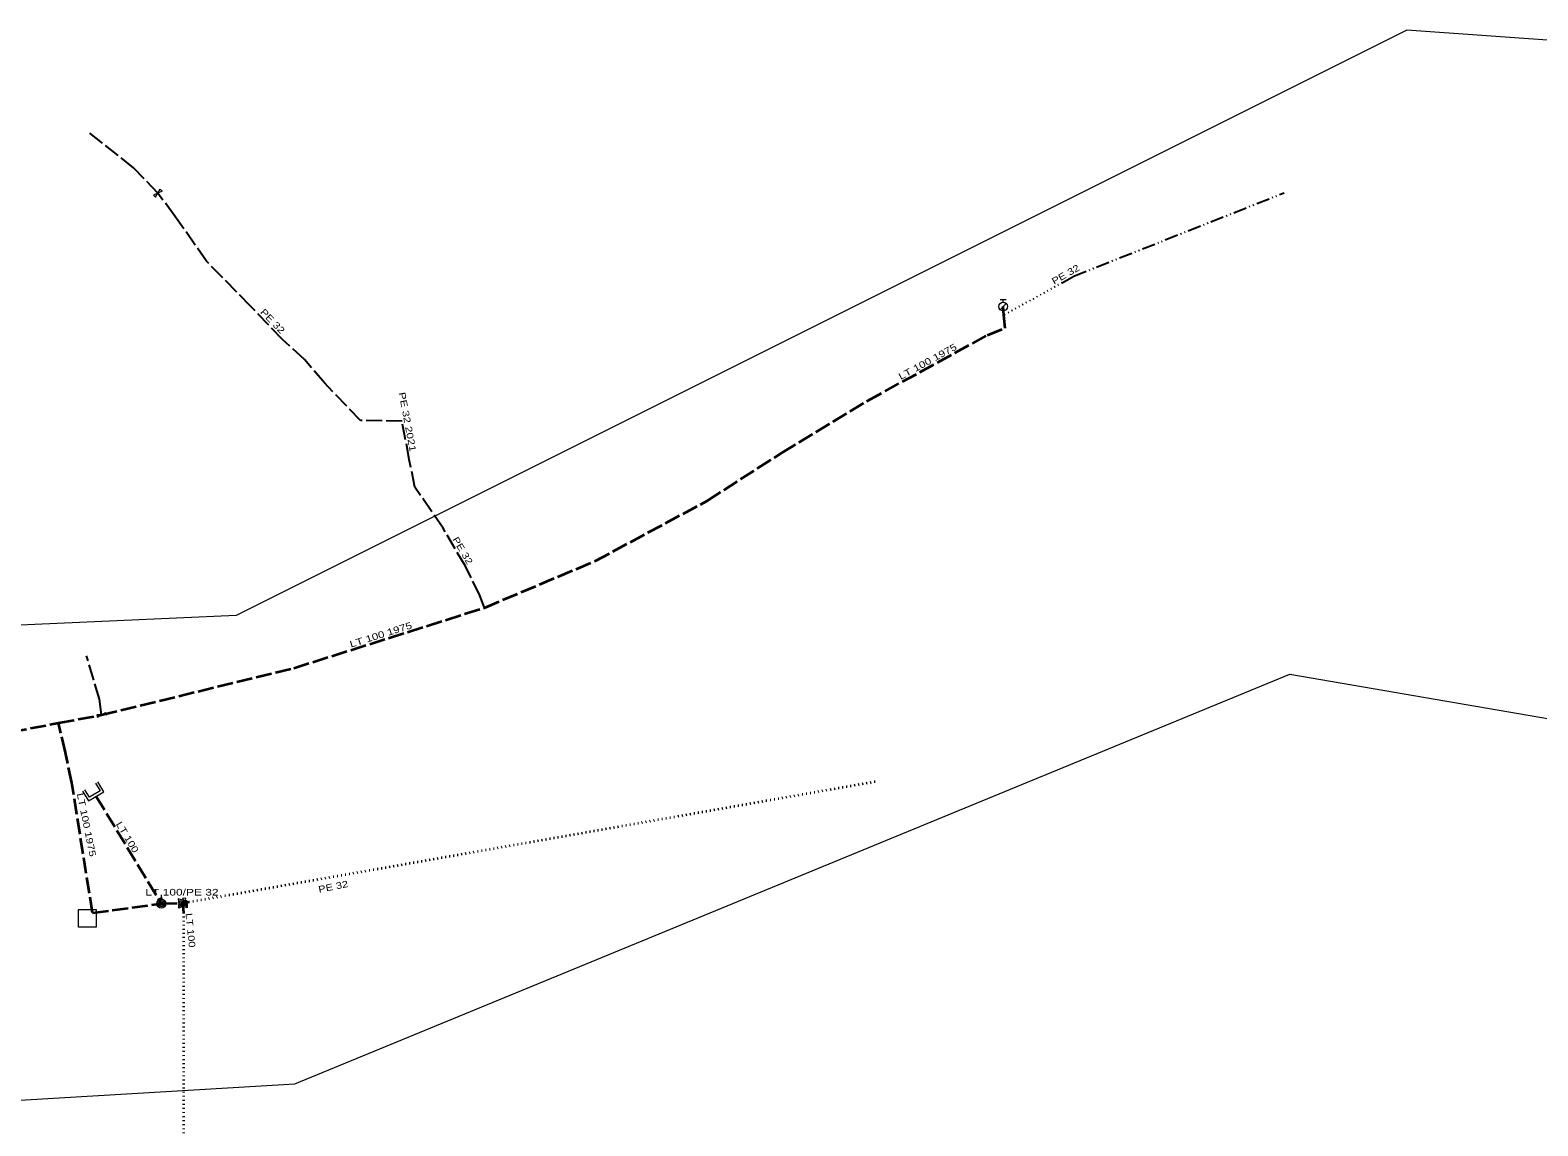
# Model space of a CAD drawing. Extents: x -582626 to -580899, y -1097611 to -1096610.
# Drawn here: x -581240 to -581069.6, y -1096737.9 to -1096614.1 of the extents above; entities that cross this region are included whole.
import ezdxf
from ezdxf.enums import TextEntityAlignment as Align

# ---------------------------------------------------------------- set-up
doc = ezdxf.new("R2010")
doc.units = 0
doc.header["$LTSCALE"] = 0.3
for name, pattern in [('DASH_DOUBLE_DOT', [9.2, 5, -1.2, 0.3, -1.2, 0.3, -1.2]), ('DOTTED', [1.5, 0.3, -1.2]), ('LONG_DASHED', [7.5, 6, -1.5])]:
    doc.linetypes.add(name, pattern=pattern)
for name, color, linetype, lineweight in [('1', 7, 'Continuous', 13), ('10', 7, 'Continuous', 13), ('35', 7, 'LONG_DASHED', 35), ('36', 7, 'DASH_DOUBLE_DOT', 35), ('45', 7, 'LONG_DASHED', 35), ('50', 7, 'LONG_DASHED', 25), ('51', 7, 'DOTTED', 25)]:
    doc.layers.add(name, color=color, linetype=linetype, lineweight=lineweight)
for name, color, linetype in [('16', 7, 'Continuous'), ('18', 7, 'Continuous'), ('19', 7, 'Continuous')]:
    doc.layers.add(name, color=color, linetype=linetype)

msp = doc.modelspace()

# ---------------------------------------------------------------- linework, layer by layer
at = {"layer": '1'}
msp.add_lwpolyline([(-582625.57, -1097394.66), (-582612.34, -1097467.421), (-582321.299, -1097262.369), (-581897.965, -1097202.837), (-581719.372, -1097182.994), (-581593.695, -1097110.233), (-581382.028, -1096971.327), (-581362.184, -1096819.192), (-581322.497, -1096739.817), (-581210.049, -1096733.202), (-581097.601, -1096686.9), (-580905.778, -1096719.973), (-580899.163, -1096627.369), (-581084.372, -1096614.14), (-581216.663, -1096680.285), (-581368.799, -1096686.9), (-581434.945, -1096812.577), (-581468.018, -1096971.327), (-581659.84, -1097004.4), (-581831.82, -1097110.233), (-582314.684, -1097169.765), (-582519.736, -1097295.442), (-582625.57, -1097394.66)], close=True, dxfattribs=at)
at = {"layer": '10'}
for p, q in [((-581130.337, -1096645.723), (-581129.63, -1096645.016)), ((-581130.333, -1096644.569), (-581129.633, -1096644.569)), ((-581129.983, -1096644.869), (-581129.983, -1096644.569)), ((-581225.134, -1096712.32), (-581225.275, -1096712.179)), ((-581222.238, -1096712.695), (-581222.262, -1096712.446)), ((-581222.691, -1096712.871), (-581222.941, -1096712.871))]:
    msp.add_line(p, q, dxfattribs=at)
for points in [[(-581225.526, -1096632.551), (-581225.246, -1096632.11), (-581225.05, -1096632.337), (-581225.526, -1096632.551), (-581226.002, -1096632.765), (-581225.806, -1096632.992)], [(-581231.902, -1096691.503), (-581231.455, -1096691.233), (-581231.38, -1096691.524), (-581231.902, -1096691.503), (-581232.424, -1096691.482), (-581232.349, -1096691.773)], [(-581223.224, -1096712.29), (-581223.126, -1096713.286), (-581221.981, -1096712.67)], [(-581223.053, -1096712.5), (-581222.999, -1096713.047), (-581222.369, -1096712.708)], [(-581232.484, -1096713.492), (-581232.484, -1096715.492), (-581234.484, -1096715.492), (-581234.484, -1096713.492)]]:
    msp.add_lwpolyline(points, close=True, dxfattribs=at)
for points in [[(-581234.023, -1096700.112), (-581233.347, -1096701.222), (-581231.639, -1096700.182), (-581232.316, -1096699.071)], [(-581232.572, -1096699.228), (-581232.051, -1096700.082), (-581233.247, -1096700.81), (-581233.767, -1096699.956)], [(-581225.134, -1096711.82), (-581225.134, -1096712.32), (-581224.993, -1096712.179)], [(-581222.487, -1096712.718), (-581222.254, -1096713.198), (-581222.626, -1096713.233), (-581222.487, -1096712.718), (-581222.348, -1096712.203), (-581222.72, -1096712.238), (-581222.487, -1096712.718), (-581222.238, -1096712.695), (-581222.215, -1096712.943)], [(-581222.691, -1096713.121), (-581222.191, -1096712.934), (-581222.191, -1096713.308), (-581222.691, -1096713.121), (-581223.191, -1096712.934), (-581223.191, -1096713.308), (-581222.691, -1096713.121), (-581222.691, -1096712.871), (-581222.441, -1096712.871)]]:
    msp.add_lwpolyline(points, dxfattribs=at)
for centre, radius in [((-581129.9828, -1096645.3687), 0.5), ((-581225.1313, -1096712.8225), 0.5), ((-581225.1313, -1096712.8225), 0.35), ((-581225.1313, -1096712.8225), 0.2)]:
    msp.add_circle(centre, radius, dxfattribs=at)
at = {"layer": '35'}
msp.add_line((-581232.901, -1096713.873), (-581225.132, -1096712.822), dxfattribs=at)
for points in [[(-581282.851, -1096698.382), (-581272.164, -1096697.829), (-581259.131, -1096695.863), (-581250.542, -1096694.672), (-581242.143, -1096693.432), (-581236.734, -1096692.413), (-581231.902, -1096691.503), (-581210.162, -1096686.212), (-581188.602, -1096679.388), (-581176.072, -1096674.108), (-581163.45, -1096667.317), (-581155.012, -1096661.891), (-581145.313, -1096656.011), (-581131.766, -1096648.598), (-581129.767, -1096647.793), (-581129.897, -1096646.337), (-581129.983, -1096645.369)], [(-581232.901, -1096713.873), (-581235.24, -1096699.193), (-581235.974, -1096695.745), (-581236.734, -1096692.413)], [(-581225.132, -1096712.822), (-581222.787, -1096712.768), (-581222.691, -1096713.121), (-581222.62, -1096713.832)], [(-581222.787, -1096712.768), (-581222.578, -1096712.729), (-581222.487, -1096712.718)]]:
    msp.add_lwpolyline(points, dxfattribs=at)
at = {"layer": '36', "linetype": 'DOTTED'}
for p, q in [((-581222.487, -1096712.718), (-581144.292, -1096698.994)), ((-581222.62, -1096713.832), (-581222.595, -1096876.348))]:
    msp.add_line(p, q, dxfattribs=at)
at = {"layer": '45'}
msp.add_line((-581232.493, -1096700.702), (-581225.132, -1096712.822), dxfattribs=at)
at = {"layer": '50'}
msp.add_line((-581123.322, -1096642.679), (-581122.008, -1096641.926), dxfattribs=at)
for points in [[(-581188.602, -1096679.388), (-581189.142, -1096678.019), (-581190.769, -1096674.686), (-581193.29, -1096670.405), (-581196.472, -1096665.771), (-581197.103, -1096662.643), (-581197.922, -1096658.322), (-581202.618, -1096658.244), (-581206.7, -1096653.995), (-581208.959, -1096651.365), (-581211.423, -1096649.098), (-581215.033, -1096645.331), (-581220.017, -1096640.257), (-581223.6, -1096635.136), (-581225.526, -1096632.551), (-581228.26, -1096629.695), (-581233.4, -1096625.614)], [(-581231.902, -1096691.503), (-581232.116, -1096689.723), (-581233.575, -1096684.844)]]:
    msp.add_lwpolyline(points, dxfattribs=at)
at = {"layer": '51', "linetype": 'DASH_DOUBLE_DOT'}
msp.add_line((-581122.008, -1096641.926), (-581098.237, -1096632.517), dxfattribs=at)
at = {"layer": '51'}
msp.add_line((-581123.322, -1096642.679), (-581129.897, -1096646.337), dxfattribs=at)

# ---------------------------------------------------------------- texts
at = {"layer": '16'}
for s, rotation, width, p in [('LT 100 1975', 28.688, 1.3, (-581138.3505, -1096651.9164)), ('LT 100 1975', 17.563, 1.3, (-581200.2087, -1096682.7996)), ('LT 100 1975', 281.533, 1.3, (-581233.952, -1096703.993)), ('PE 32', 11.319, 1.25, (-581205.6281, -1096711.2693)), ('LT 100', 275.703, 1.25, (-581222.2021, -1096715.8737))]:
    msp.add_text(s, height=0.75, rotation=rotation, dxfattribs=dict(at, width=width)).set_placement(p, align=Align.CENTER)
at = {"layer": '16', "width": 1.35}
msp.add_text('LT 100/PE 32', height=0.75, dxfattribs=at).set_placement((-581222.7935, -1096711.91), align=Align.CENTER)
at = {"layer": '18', "width": 1.25}
msp.add_text('LT 100', height=0.75, rotation=301.272, dxfattribs=at).set_placement((-581229.2842, -1096705.5048), align=Align.CENTER)
at = {"layer": '19'}
for s, rotation, width, p in [('PE 32', 29.815, 1.25, (-581122.7435, -1096642.059)), ('PE 32', 313.781, 1.25, (-581212.8216, -1096647.278)), ('PE 32 2021', 280.732, 1.3, (-581197.6764, -1096658.4642)), ('PE 32', 300.493, 1.25, (-581191.3945, -1096673.1302))]:
    msp.add_text(s, height=0.75, rotation=rotation, dxfattribs=dict(at, width=width)).set_placement(p, align=Align.CENTER)

doc.saveas('drawing.dxf')
